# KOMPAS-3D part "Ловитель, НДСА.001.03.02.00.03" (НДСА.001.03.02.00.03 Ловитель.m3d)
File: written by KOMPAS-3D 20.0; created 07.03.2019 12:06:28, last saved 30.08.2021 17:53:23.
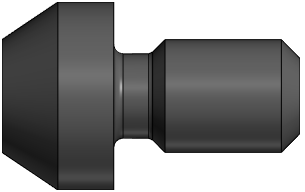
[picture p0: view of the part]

Document properties: Автор: Пользователь Windows; Полное имя файла: C:\Users\korychko\Desktop\PLM\НДСА.001.03.02.00.03 - Ловитель.m3d

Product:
- Part/product: Ловитель  | designation НДСА.001.03.02.00.03
    Материал: Сталь 12Х18Н10Т ГОСТ 5632-2014 (density 7900 kg/m3)
    Масса: 0.00501766
    additional columns: <item xmlns="http://appius.ru/pdm" xmlns:xs="http://www.w3.org/2001/XMLSchema" x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; <item xmlns="http://appius.ru/pdm" xmlns:xs="http://www.w3.org/2001/XMLSchema" x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; <item xmlns="http://appius.ru/pdm" xmlns:xs="http://www.w3.org/2001/XMLSchema" x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; <item xmlns="http://appius.ru/pdm" xmlns:xs="http://www.w3.org/2001/XMLSchema" x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; <item xmlns="http://appius.ru/pdm" xmlns:xs="http://www.w3.org/2001/XMLSchema" x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; <item xmlns="http://appius.ru/pdm" xmlns:xs="http://www.w3.org/2001/XMLSchema" x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; <item xmlns="http://appius.ru/pdm" xmlns:xs="http://www.w3.org/2001/XMLSchema" x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; <item xmlns="http://appius.ru/pdm" xmlns:xs="http://www.w3.org/2001/XMLSchema" x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
    source file: НДСА.001.03.02.00.03 - Ловитель.cdw

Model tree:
1. Эскиз:1
2. Элемент вращения:1
     Угол 1 = 360
3. Условное изображение резьбы:2  (with: Элемент вращения:1)  (labels: M6; cil0_24705-2004 coarse)
     Длина резьбы = 8; Шаг резьбы = 1; Номинальный диаметр резьбы = 6
4. Подгонка:1  (with: Элемент вращения:1)
5. Фаска:2  (with: Элемент вращения:1)
     Угол = 45; Длина 1 = 1; Длина 2 = 1
6. Ось конической поверхности:1  (with: Элемент вращения:1)
7. Смещенная плоскость:1  (with: Элемент вращения:1)
8. ЛСК:1  (with: Плоскость XY, Плоскость ZX, Плоскость ZY, Ось X, Ось Y, Ось Z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)
     Ось X. Y = 1; Ось Y. X = -1; Ось Z. Z = 1; Точка начала. Y = 8
9. Эскиз:2
10. Эскиз:3
11. Элемент вращения:2
     Угол 1 = 360
12. Элемент вращения:3
     Угол 1 = 360
13. Проточка наружная M6x1 У ГОСТ 10549-80  (labels: Сталь 12Х18Н10Т ГОСТ 5632-2014)

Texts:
  KTE.LIST=Du7ArA6Td4KLoATnVjMlQc; KTE.LIST=gVt5qV3zafSUUmu7llP6.d
  Edge1
  Edge2
  НДСА.001.03.02.00.03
